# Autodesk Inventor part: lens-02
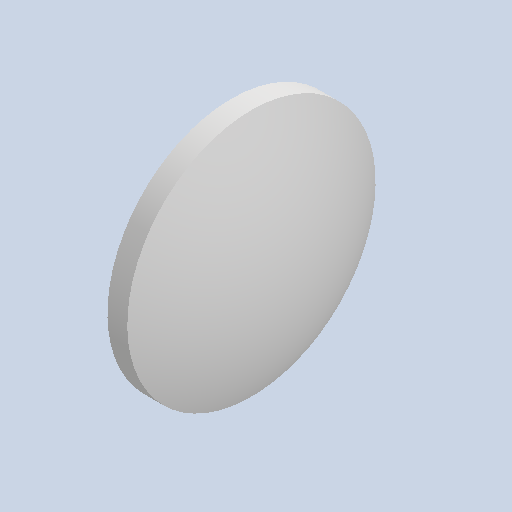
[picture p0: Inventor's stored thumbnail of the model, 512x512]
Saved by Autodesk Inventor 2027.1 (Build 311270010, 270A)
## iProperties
Created: 2026-07
Part Number: lens-02
Material: Generic
Document SubType Name: Modeling
Designer: dunge
Density: 1 g/cm^3
Appearance: Default
Author: dunge
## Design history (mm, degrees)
derived "lens.ipt"
feature "Lens::lens.ipt"
tag "TaggingFeature1"
node "Finishes"
node "Lens"
node "Finish1" dims "Finish1_Area" = 277.03218
other parameters: "SIDE_2_MINOR" = 1.524, "LENS_RADIUS" = 19.05, "SIDE_1_MINOR" = 1.524, "SIDE_1_MAJOR" = 7.62, "SIDE_2_MAJOR" = 3.175
